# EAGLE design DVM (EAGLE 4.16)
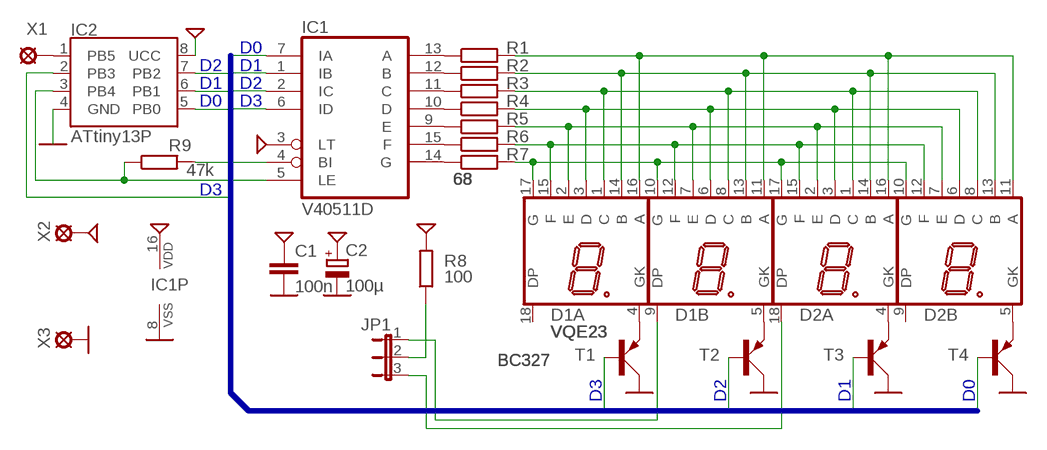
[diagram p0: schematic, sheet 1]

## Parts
C1  100n  C0805  [0805]
C2  100µ  E5-10R  [E5-10,5R]
D1  VQE23  [VQE]
D2  VQE23  [VQE]
IC1  V40511D  4511N  [DIL16]
IC2  ATtiny13P  ATTINY13P  [DIL08]
JP1  JP2E  [JP2]
R1  68  R0805  [0805]
R2  68  R0805  [0805]
R3  68  R0805  [0805]
R4  68  R0805  [0805]
R5  68  R0805  [0805]
R6  68  R0805  [0805]
R7  68  R0805  [0805]
R8  100  R0805  [0805]
R9  47k  R0805  [0805]
T1  BC327  PNPS  [SOT23]
T2  BC327  PNPS  [SOT23]
T3  BC327  PNPS  [SOT23]
T4  BC327  PNPS  [SOT23]
X1  PAD  [LSP11]
X2  PAD  [LSP11]
X3  PAD  [LSP11]

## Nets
5P: C1.1 C2.+ IC1.3(LT) IC1.16(VDD) IC2.8(UCC) R8.2 X2.MP
A: D1.11(B:A) D1.16(A:A) D2.11(B:A) D2.16(A:A) R1.2
B: D1.13(B:B) D1.14(A:B) D2.13(B:B) D2.14(A:B) R2.2
C: D1.1(A:C) D1.8(B:C) D2.1(A:C) D2.8(B:C) R3.2
D: D1.3(A:D) D1.6(B:D) D2.3(A:D) D2.6(B:D) R4.2
D0: IC1.7(IA) IC2.5(PB0) T4.1(B)
D1: IC1.1(IB) IC2.6(PB1) T3.1(B)
D2: IC1.2(IC) IC2.7(PB2) T2.1(B)
D3: IC1.6(ID) IC2.2(PB3) T1.1(B)
E: D1.2(A:E) D1.7(B:E) D2.2(A:E) D2.7(B:E) R5.2
F: D1.12(B:F) D1.15(A:F) D2.12(B:F) D2.15(A:F) R6.2
G: D1.10(B:G) D1.17(A:G) D2.10(B:G) D2.17(A:G) R7.2
GND: C1.2 C2.- IC1.8(VSS) IC2.4(GND) T1.3(C) T2.3(C) T3.3(C) T4.3(C) X3.MP
K0: D2.5(B:GK) T4.2(E)
K1: D2.4(A:GK) T3.2(E)
K2: D1.5(B:GK) T2.2(E)
K3: D1.4(A:GK) T1.2(E)
N$1: IC1.13(A) R1.1
N$2: IC1.12(B) R2.1
N$3: IC1.11(C) R3.1
N$4: IC1.10(D) R4.1
N$5: IC1.9(E) R5.1
N$6: IC1.15(F) R6.1
N$7: IC1.14(G) R7.1
N$8: IC1.4(BI) R9.2
N$9: D2.18(A:DP) JP1.3
N$10: IC2.1(PB5) X1.MP
N$11: D1.9(B:DP) JP1.1
N$12: JP1.2 R8.1
N$13: IC1.5(LE) IC2.3(PB4) R9.1
Unconnected: D1.18(A:DP) D2.9(B:DP)

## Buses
D[0..3]

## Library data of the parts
C1 = hv:C: Kondensator
C2 = hv:E: Elektrolytkondensator
D1 D2 = statron:VQE*3: LED-Anzeige 2 Zeichen 7-Segment mit Dezimalpunkt, VQE13: rot, gemeinsame Katode VQE23: grün, gemeinsame Katode
IC1 = 45xx:4511: BCD to 7-segment LATCH/DECODER/DRIVER
IC2 = statron:ATTINY13*: AVR-8-bit-Mikrocontroller 64 Byte RAM 64 Byte EEPROM 1 KByte Flash max. 20 MHz 1 8-bit-Timer 10-bit-A/D-Wandler, 4 Eingänge Analogvergleicher Anschlüsse speziell für Rundumleuchte!
JP1 = jumper:JP2E: JUMPER
R1-R9 = hv:R: Widerstand
T1-T4 = UZD1:PNP: pnp-Transistor
X1-X3 = statron:PAD: Lötanschluss

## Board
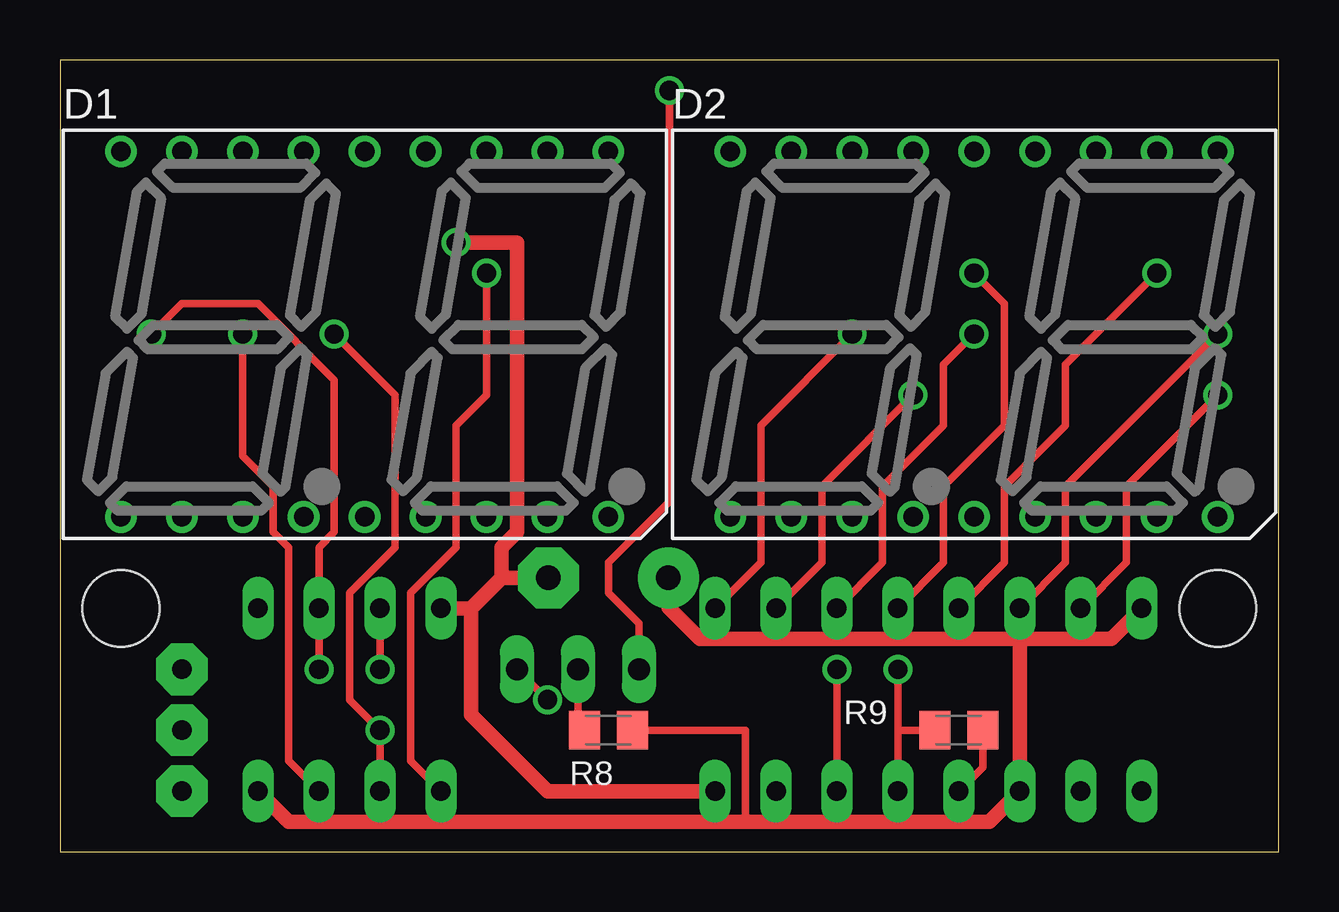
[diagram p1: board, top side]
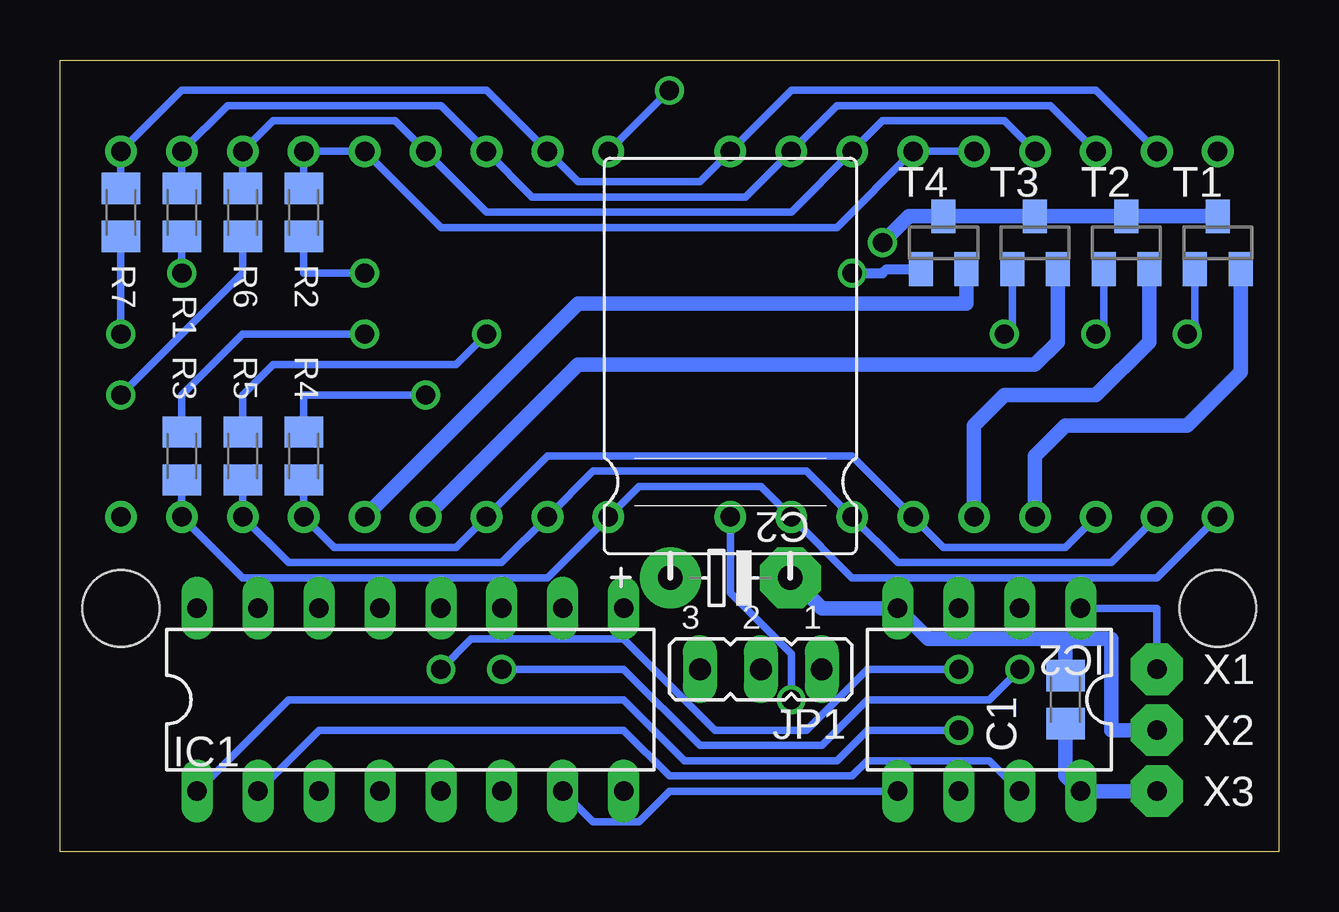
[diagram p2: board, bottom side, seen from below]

Size 50.8 x 33.02 mm. Coordinates in mm from the lower left corner, seen from the top.
Outline: 0,0 50.8,0 50.8,33.02 0,33.02 0,0
Copper layers (1+16): Top 0.035mm / dielectric 1.5mm / Bottom 0.035mm
Design rules "default": minimum track width 10mil, minimum drill 24mil, track to track 8mil, track to pad 8mil, pad to pad 8mil, via to via 8mil, smd to smd 8mil, copper to edge 10mil, drill to drill 8mil, minimum pad ring 10mil, minimum via ring 8mil, stop-mask expansion 4mil, vias tented up to drill 0mil, thermal gap 10mil
Holes 3.2 mm at 2.54,10.16 48.26,10.16

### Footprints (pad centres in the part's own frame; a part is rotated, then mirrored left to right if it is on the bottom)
0805 = smd 1.3 x 1.6: 1 -1,0; 2 1,0
E5-10,5R = drill 1.016 pad 2.54 round: + -2.5,0 | drill 1.016 pad 2.54 octagon: - 2.5,0
VQE = drill 0.813 round: 1 -10.16,-7.62; 2 -7.62,-7.62; 3 -5.08,-7.62; 4 -2.54,-7.62; 5 0,-7.62; 6 2.54,-7.62; 7 5.08,-7.62; 8 7.62,-7.62; 9 10.16,-7.62; 10 10.16,7.62; 11 7.62,7.62; 12 5.08,7.62; 13 2.54,7.62; 14 0,7.62; 15 -2.54,7.62; 16 -5.08,7.62; 17 -7.62,7.62; 18 -10.16,7.62
DIL16 = drill 0.813 long: 1 -8.89,-3.81; 2 -6.35,-3.81; 3 -3.81,-3.81; 4 -1.27,-3.81; 5 1.27,-3.81; 6 3.81,-3.81; 7 6.35,-3.81; 8 8.89,-3.81; 9 8.89,3.81; 10 6.35,3.81; 11 3.81,3.81; 12 1.27,3.81; 13 -1.27,3.81; 14 -3.81,3.81; 15 -6.35,3.81; 16 -8.89,3.81
DIL08 = drill 0.813 long: 1 -3.81,-3.81; 2 -1.27,-3.81; 3 1.27,-3.81; 4 3.81,-3.81; 5 3.81,3.81; 6 1.27,3.81; 7 -1.27,3.81; 8 -3.81,3.81
JP2 = drill 0.914 long: 1 -2.54,0; 2 0,0; 3 2.54,0
SOT23 = smd 1 x 1.4: 1 -0.95,-1.1; 2 0.95,-1.1; 3 0,1.1
LSP11 = drill 0.813 pad 2.159 octagon: MP 0,0

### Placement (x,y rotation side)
C1  8.89,6.35 90 bottom
C2  22.86,11.43 0 bottom
D1  12.7,21.59 0 top
D2  38.1,21.59 0 top
IC1  36.2,6.35 0 bottom
IC2  12.06,6.35 180 bottom
JP1  21.59,7.62 180 bottom
R1  45.72,26.67 90 bottom
R2  40.64,26.67 90 bottom
R3  45.72,16.51 270 bottom
R4  40.64,16.51 270 bottom
R5  43.18,16.51 270 bottom
R6  43.18,26.67 90 bottom
R7  48.26,26.67 90 bottom
R8  22.86,5.08 0 top
R9  37.47,5.08 0 top
T1  2.54,25.4 0 bottom
T2  6.35,25.4 0 bottom
T3  10.16,25.4 0 bottom
T4  13.97,25.4 0 bottom
X1  5.08,7.62 0 bottom
X2  5.08,2.54 0 bottom
X3  5.08,5.08 0 bottom

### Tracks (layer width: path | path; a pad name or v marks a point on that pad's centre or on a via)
5P
  Top 0.305: R8.2 28.57,5.08 28.57,1.27
  Top 0.61: IC2.8 9.53,1.27 28.57,1.27 38.73,1.27 IC1.3 40.01,8.89 | 40.01,8.89 43.81,8.89 IC1.16 | 40.01,8.89 26.67,8.89 25.36,10.2 C2.+
  Bottom 0.61: X2.MP IC2.8 8.89,3.17 C1.1
A
  Bottom 0.305: D1.16 9.53,31.11 18.41,31.11 D1.11 22.23,27.3 31.11,27.3 D2.16 34.92,31.11 43.81,31.11 D2.11 R1.2
B
  Bottom 0.305: D1.14 D1.13 18.41,26.04 34.92,26.04 D2.14 D2.13 R2.2
C
  Bottom 0.305: D1.1 5.08,11.43 17.78,11.43 D1.8 21.59,15.24 26.67,15.24 D2.1 30.48,11.43 43.18,11.43 D2.8 R3.2
D
  Bottom 0.305: D1.3 8.89,12.7 13.97,12.7 D1.6 17.78,16.51 30.48,16.51 D2.3 34.29,12.7 39.37,12.7 D2.6 R4.2
D0  (via drill 0.8 pad 0.8)
  Top 0.305: IC2.5 14.61,3.81 14.61,10.79 16.51,12.7 16.51,17.78 17.78,19.05 v17.78,24.13
  Bottom 0.305: IC2.5 25.4,2.54 26.67,1.27 28.57,1.27 IC1.7
  Bottom 0.406: T4.1 16.34,24.3 16.51,24.13 v17.78,24.13
D1  (via drill 0.8 pad 0.8)
  Top 0.305: v11.43,21.59 13.97,19.05 13.97,12.7 12.06,10.79 12.06,6.35 v13.34,5.08 IC2.6
  Bottom 0.305: v13.34,5.08 17.14,5.08 18.41,3.81 24.77,3.81 27.3,6.35 41.27,6.35 IC1.1 | T3.1 11.11,21.91 v11.43,21.59
D2  (via drill 0.8 pad 0.8)
  Top 0.305: v7.62,21.59 7.62,16.51 8.89,15.24 8.89,13.34 9.53,12.7 9.53,3.81 IC2.7
  Bottom 0.305: IC1.2 40.01,5.08 27.3,5.08 25.4,3.17 17.78,3.17 17.14,3.81 12.06,3.81 IC2.7 | T2.1 7.3,21.91 v7.62,21.59
D3  (via drill 0.8, 0.8 pad 0.8)
  Top 0.305: v3.81,21.59 5.08,22.86 8.26,22.86 11.43,19.68 11.43,13.34 10.79,12.7 IC2.2 v10.79,7.62 | v32.38,7.62 IC1.6
  Bottom 0.305: v10.79,7.62 12.06,6.35 17.14,6.35 19.05,4.45 24.13,4.45 27.3,7.62 v32.38,7.62 | 3.49,21.91 T1.1
  Bottom 0.406: v3.81,21.59 3.49,21.91
E
  Bottom 0.305: D1.2 6.99,12.06 15.88,12.06 D1.7 19.68,15.88 28.57,15.88 D2.2 32.38,12.06 41.27,12.06 D2.7 R5.2
F
  Bottom 0.305: D1.15 11.43,30.48 16.51,30.48 D1.12 20.32,26.67 33.02,26.67 D2.15 36.83,30.48 41.91,30.48 D2.12 R6.2
G
  Bottom 0.305: D1.17 7.62,31.75 20.32,31.75 D1.10 24.13,27.94 29.21,27.94 D2.17 33.02,31.75 45.72,31.75 D2.10 R7.2
GND  (via drill 0.8)
  Top 0.305: 20.32,11.43 C2.-
  Top 0.61: IC1.8 20.32,2.54 17.14,5.71 17.14,10.16 | v16.51,25.4 19.05,25.4 19.05,13.34 18.41,12.7 18.41,11.43 | 17.14,10.16 18.41,11.43 | IC2.4 17.14,10.16 | 18.41,11.43 20.32,11.43
  Bottom 0.61: T1.3 T2.3 T3.3 T4.3 15.41,26.5 v16.51,25.4 | X3.MP 6.99,5.08 6.99,8.89 8.89,8.89 | 8.89,8.89 14.61,8.89 IC2.4 19.05,10.16 20.32,11.43 C2.- | 8.89,8.89 C1.2
K0
  Bottom 0.61: T4.2 13.02,22.86 29.21,22.86 D2.5
K1
  Bottom 0.61: T3.2 9.21,21.27 10.16,20.32 29.21,20.32 D2.4
K2
  Bottom 0.61: T2.2 5.4,21.27 7.62,19.05 11.43,19.05 12.7,17.78 D1.5
K3
  Bottom 0.61: T1.2 1.59,20 3.81,17.78 8.89,17.78 10.16,16.51 D1.4
N$1  (via drill 0.8 pad 0.8)
  Top 0.305: v45.72,24.13 41.91,20.32 41.91,17.78 39.37,15.24 39.37,12.06 IC1.13
  Bottom 0.305: v45.72,24.13 R1.1
N$2  (via drill 0.8 pad 0.8)
  Top 0.305: v38.1,24.13 39.37,22.86 39.37,17.78 36.83,15.24 36.83,12.06 IC1.12
  Bottom 0.305: R2.1 40.64,24.13 v38.1,24.13
N$3  (via drill 0.8 pad 0.8)
  Top 0.305: v38.1,21.59 36.83,20.32 36.83,17.78 34.29,15.24 34.29,12.06 IC1.11
  Bottom 0.305: R3.1 45.72,19.05 43.18,21.59 v38.1,21.59
N$4  (via drill 0.8 pad 0.8)
  Top 0.305: v35.56,19.05 31.75,15.24 31.75,12.06 IC1.10
  Bottom 0.305: R4.1 40.64,19.05 v35.56,19.05
N$5  (via drill 0.8 pad 0.8)
  Top 0.305: v33.02,21.59 29.21,17.78 29.21,12.06 IC1.9
  Bottom 0.305: R5.1 43.18,19.05 41.91,20.32 34.29,20.32 v33.02,21.59
N$6  (via drill 0.8 pad 0.8)
  Top 0.305: IC1.15 44.45,12.06 44.45,15.24 v48.26,19.05
  Bottom 0.305: R6.1 43.18,24.13 v48.26,19.05
N$7  (via drill 0.8 pad 0.8)
  Top 0.305: IC1.14 41.91,12.06 41.91,15.24 v48.26,21.59
  Bottom 0.305: v48.26,21.59 R7.1
N$8
  Top 0.305: R9.2 38.47,3.54 IC1.4
N$9  (via drill 0.8)
  Top 0.305: JP1.3 24.13,9.53 22.86,10.79 22.86,12.06 25.4,14.61 v25.4,31.75
  Bottom 0.305: v25.4,31.75 D2.18
N$10
  Bottom 0.305: X1.MP 5.08,10.16 IC2.1
N$11  (via drill 0.8)
  Top 0.305: JP1.1 v20.32,6.35
  Bottom 0.305: D1.9 22.86,10.79 20.32,8.26 v20.32,6.35
N$12
  Top 0.305: R8.1 21.59,5.08 JP1.2
N$13  (via drill 0.8, 0.8 pad 0.8)
  Top 0.305: 34.92,5.08 IC1.5 | 34.92,5.08 R9.1 | v34.92,7.62 34.92,5.08 | v13.34,7.62 IC2.3
  Bottom 0.305: v13.34,7.62 17.14,7.62 19.68,5.08 23.5,5.08 27.3,8.89 33.66,8.89 v34.92,7.62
